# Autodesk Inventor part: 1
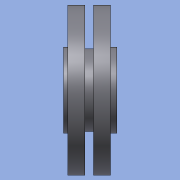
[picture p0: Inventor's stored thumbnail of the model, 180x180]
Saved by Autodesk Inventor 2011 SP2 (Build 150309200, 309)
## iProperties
Created: 2013-10
Part Number: 1
Material: 1.0570 St 52-3
Document SubType Name: Modeling
Density: 7.84 g/cm^3
Mass: 327518 g
Surface Area: 13235.4 cm^2
Volume: 41775.3 cm^3
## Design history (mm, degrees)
sketch "Skizze1"
  geometry: L1 (-2779.874, 0)-(4908.06, 0) reference; L2 (0, -1325.567)-(0, 2905.542) reference; L3 (130, 203)-(130, 112); L4 (130, 203)-(100, 203); L5 (100, 203)-(100, 400); L6 (100, 400)-(20, 400); L7 (20, 400)-(20, 195); L8 (20, 195)-(-20, 195); L9 (-20, 195)-(-20, 400); L10 (-20, 400)-(-100, 400); L11 (-100, 400)-(-100, 203); L12 (-100, 203)-(-120, 203); L13 (-120, 203)-(-120, 112); L14 (-120, 112)-(130, 112); L15 (0, 2301.098)-(0, 524.244); L16 (-1681.598, 0)-(3809.784, 0); L17 (0, 1061.702)-(0, -721.123); 2 further points
  constraints: 30 end point, 8 parallel, 5 point on line, 4 collinear, 4 perpendicular, 1 midpoint, 1 other
  dimensions: "d3" = 40 distance between parallel lines of L7 L9; "d4" = 200 distance between parallel lines of L5 L11; "d5" = 112 distance between parallel lines of L16 L14; "d6" = 203 distance between parallel lines of L16 L4; "d7" = 120 distance between parallel lines of L17 L13; "d8" = 195 distance between parallel lines of L16 L8; "d9" = 400 distance between parallel lines of L16 L6; "d16" = 130 distance between parallel lines of L3 L17
revolve "Umdrehung1" sketch "Skizze1" stored, may be unused: angle "d10" = 180 deg
workplane "Arbeitsebene1"
sketch "Skizze2"
  geometry: L1 (230, -91)-(230, -288) reference; L2 (230, -288)-(150, -288) reference; L3 (150, -288)-(150, -83) reference; L4 (150, -83)-(110, -83) reference; L5 (110, -83)-(110, -288) reference; L6 (110, -288)-(30, -288) reference; L7 (30, -288)-(30, -91) reference; L8 (30, -91)-(0, -91) reference; L9 (0, -91)-(0, 0) reference; L10 (0, 0)-(250, 0) reference; L11 (250, 0)-(250, -91) reference; L12 (250, -91)-(230, -91) reference; L13 (250, 224)-(250, 315) reference; L14 (0, 224)-(250, 224) reference; L15 (250, 315)-(230, 315) reference; L16 (230, 315)-(230, 512) reference; L17 (150, 512)-(150, 307) reference; L18 (150, 307)-(110, 307) reference; L19 (110, 307)-(110, 512) reference; L20 (30, 512)-(30, 315) reference; L21 (30, 315)-(0, 315) reference; L22 (0, 315)-(0, 224) reference; L23 (0, 315)-(0, 224) reference; L24 (0, 224)-(250, 224) reference; L25 (250, 224)-(250, 315) reference; L26 (250, 315)-(230, 315) reference; L27 (230, 315)-(230, 512) reference; L28 (230, 512)-(150, 512) reference; L29 (150, 512)-(150, 307) reference; L30 (150, 307)-(110, 307) reference; L31 (110, 307)-(110, 512) reference; L32 (110, 512)-(30, 512) reference; L33 (30, 512)-(30, 315) reference; L34 (30, 315)-(0, 315) reference; L35 (110, 512)-(30, 512) reference; 1 further point
extrude "Extrusion1" join sketch "Skizze2" distance "d12" = 8; taper "d13" = 0 deg
node "Volumenkörper1"
node "Projizierte Kontur1"
other parameters: "d11" = 0
